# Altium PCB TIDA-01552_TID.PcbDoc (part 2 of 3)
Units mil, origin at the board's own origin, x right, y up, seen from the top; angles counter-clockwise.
Board outline 6250 x 2150 mil, 4 copper layers (Top Layer, Signal Layer 1, Signal Layer 2, Bottom Layer), stack 62.6 mil thick; 251 components, 249 nets, 926 pads, 730 vias.
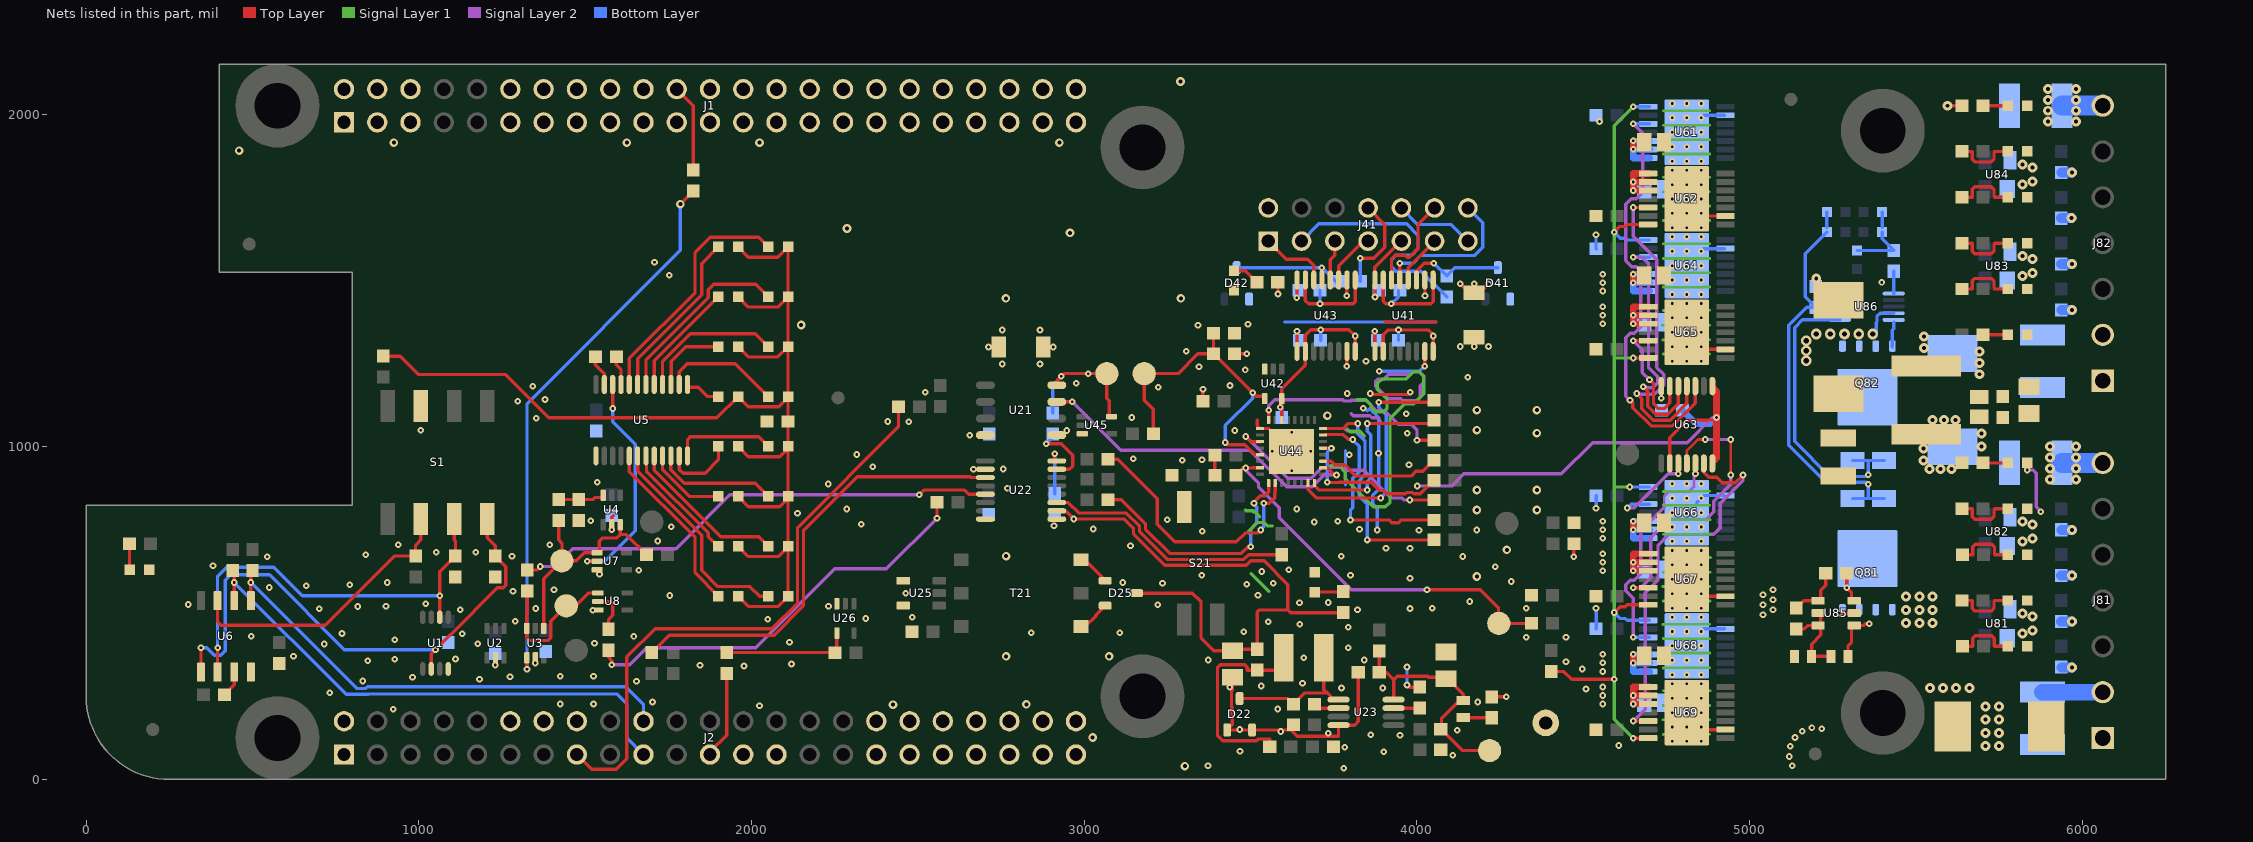
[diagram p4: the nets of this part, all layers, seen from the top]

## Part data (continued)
R75: "RES, 16.5 k, 1%, 0.1 W, 0603", Manufacturer=Vishay-Dale, Power_W=0.1, Supplier Part Number 1=541-16.5KHCT-ND, TempCo="100 ppm/C", Tolerance_%=1, Value1=1%, Value2=0.1W, Value_Code=16k5, ValueDisplayed=16.5k
R80 R82: "RES, 249, 1%, 0.1 W, 0603", Manufacturer=Vishay-Dale, Power_W=0.1, Supplier Part Number 1=541-249HCT-ND, TempCo="100 ppm/C", Tolerance_%=1, Value1=1%, Value2=0.1W, Value_Code=249R, ValueDisplayed=249
R83 R84 R85 R86 R87 R88 R89 R90 R91 R100: "RES, 10.0k ohm, 1%, 0.1W, 0603", Manufacturer=Vishay-Dale, Power_W=0.1, Supplier Part Number 1=541-10.0KHCT-ND, TempCo="100 ppm/C", Tolerance_%=1, Value1=1%, Value2=0.1W, Value_Code=10k0
R92: "RES, 95.3k ohm, 1%, 0.1W, 0603", Manufacturer=Vishay-Dale, Power_W=0.1, Supplier Part Number 1=541-95.3KHCT-ND, TempCo="100 ppm/C", Tolerance_%=1, Value1=1%, Value2=0.1W, Value_Code=95k3
R93: "RES, 8.06k ohm, 1%, 0.1W, 0603", Manufacturer=Vishay-Dale, Power_W=0.1, Supplier Part Number 1=541-8.06KHCT-ND, TempCo="100 ppm/C", Tolerance_%=1, Value1=1%, Value2=0.1W, Value_Code=8k06
R94: "RES, 47.5k ohm, 1%, 0.1W, 0603", Manufacturer=Vishay-Dale, Power_W=0.1, Supplier Part Number 1=541-47.5KHCT-ND, TempCo="100 ppm/C", Tolerance_%=1, Value1=1%, Value2=0.1W, Value_Code=47k5
R95: "RES, 14.0k ohm, 1%, 0.1W, 0603", Manufacturer=Vishay-Dale, Power_W=0.1, Supplier Part Number 1=541-14.0KHCT-ND, TempCo="100 ppm/C", Tolerance_%=1, Value1=1%, Value2=0.1W, Value_Code=14k0
R96: "RES, 57.6k ohm, 1%, 0.1W, 0603", Manufacturer=Vishay-Dale, Power_W=0.1, Supplier Part Number 1=541-57.6KHCT-ND, TempCo="100 ppm/C", Tolerance_%=1, Value1=1%, Value2=0.1W, Value_Code=57k6
R97: "RES, 100 ohm, 1%, 0.1W, 0603", Manufacturer=Vishay-Dale, Power_W=0.1, Supplier Part Number 1=541-100HCT-ND, TempCo="100 ppm/C", Tolerance_%=1, Value1=1%, Value2=0.1W, Value_Code=100R
R98 R99: "RES, 0.01 ohm, 1%, 1W, 1206", Manufacturer=Vishay-Dale, Power_W=1, Supplier Part Number 1=WSLP-.01CT-ND, TempCo="75 ppm/C", Value1=1%, Value2=1W, Value_Code=R010
S1: "Switch, SPST 4 Pos, Top Actuated, SMT", CurrentRating_mA=100, Manufacturer="CTS Electrocomponents", Supplier Part Number 1=CT2194LPST-ND
S21: "Switch, Slide, SPST 2 poles, SMT", CurrentRating_mA=100, Manufacturer="CTS Electrocomponents", Supplier Part Number 1=CT2192LPST-ND
T21: "Transformer, 475uH, SMT", Manufacturer="Wurth Elektronik", Supplier Part Number 1=732-4458-1-ND
TP1 TP2 TP3 TP4 TP21 TP22 TP42 TP61 TP62 TP64: library part PogoPad, "Pad for Pogo Pin Connector"
TP41: "Test Point, Miniature, Black, TH", Manufacturer=Keystone, Supplier Part Number 1=5001K-ND
U1: "Dual 2-Input Exclusive-OR Gate, DCT0008A", Alternate Manufacturer="Texas Instruments"
U2: "Single 3-Input Positive-OR Gate, DCK0006A", Alternate Manufacturer="Texas Instruments"
U3: "1-OF-2 DECODER/DEMULTIPLEXER, DCK0006A", Alternate Manufacturer="Texas Instruments"
U4: "Configurable Multiple-Function Gate, DCK0006A", Alternate Manufacturer="Texas Instruments"
U5: "16-Channel Constant Current LED Driver with LED Open Detection, 3 to 5.5 V, -40 to 85 degC, 24-pin SOP (DBQ24), Green (RoHS & no Sb/Br)", Alternate Manufacturer=None, Alternate PartNumber=Equivalent, Manufacturer="Texas Instruments", Rating=Catalog, Supplier Part Number 1=296-34376-5-ND
U6: "256 kb I2C CMOS Serial EEPROM, SOIC-8", Manufacturer="ON Semiconductor", Supplier Part Number 1=CAT24C256WI-G-ND
U7 U8: "Single Bus Buffer Gate With 3-State Output, DCK0005A", Alternate Manufacturer="Texas Instruments", Alternate PartNumber=SN74LVC1G125DCKT
U21: "1 Mbps Dual Channels, 1 / 1, Digital Isolator, 3.3 V / 5 V, -40 to +105 degC, 8-pin SOIC (D), Green (RoHS & no Sb/Br)", Alternate Manufacturer=None, Alternate PartNumber=Equivalent, Insulation Rating(VRMS)=2500, Manufacturer="Texas Instruments", Rating=Catalog, Supplier Part Number 1=ISO7421DR-ND, Supply Voltage(s)(V)="3.3, 5"
U22 U41: "4242-VPK Small-Footprint and Low-Power Quad Channels Digital Isolators, DBQ0016A", Alternate Manufacturer="Texas Instruments", Alternate PartNumber=ISO7141CCDBQ
U23: "150 mA, 100V Step-Down Switching Regulator, 8-pin MSOP, Pb-Free", Manufacturer="Texas Instruments", PackageTopMarking=ZXTT*SLLB, PowerWise=Y, Supplier Part Number 1=LM5009MMTR-ND
U25: "Low-Noise 350 mA, 410 kHz Transformer Driver, DBV0005A (SOT-23-5)", Alternate Manufacturer="Texas Instruments", Alternate PartNumber=SN6501DBVT
U26 U42 U45: "SINGLE BUFFER/DRIVER WITH OPEN-DRAIN OUTPUT, DCK0005A (SOT-SC70-5)", Alternate Manufacturer="Texas Instruments", Alternate PartNumber=SN74LVC1G07DCKT
U43: "4242-VPK Small-Footprint and Low-Power Quad Channels Digital Isolators, DBQ0016A", Alternate Manufacturer="Texas Instruments", Alternate PartNumber=ISO7141FCCDBQ
U44: "16 MHz Mixed Signal Microcontroller with 2 KB Flash, 256 B SRAM and 24 GPIOs, -40 to 105 degC, 32-pin QFN (RHB), Green (RoHS & no Sb/Br)", Alternate Manufacturer="Texas Instruments", Alternate PartNumber=Equivalent, Frequency(MHz)=16, Pin/Package="28TSSOP, 32QFN, 32WQFN", Temp Sensor=Yes
U61 U62 U64 U65 U66 U67 U68 U69: library part CMP-0077266-1, "40 V, 80 mOhm Single-Channel High-Side Switch, PWP0014C (TSSOP-14)", Alternate Manufacturer="Texas Instruments", Alternate PartNumber=TPS27S100BPWPT
U63: "8-BIT PARALLEL-OUT SERIAL SHIFT REGISTERS, PW0014A", Alternate Manufacturer="Texas Instruments", Alternate PartNumber=SN74LV164APWT
U81 U82 U83 U84: "ESD Suppressor Diode Arrays, 70V, SMD", Manufacturer=Littelfuse, Supplier Part Number 1=F5915CT-ND
U85: "LM5050-1 High Side OR-ing FET Controller, DDC0006A", Alternate Manufacturer=None, Manufacturer="Texas Instruments"
U86: "Positive High Voltage Hot Swap / Inrush Current Controller with Power Limiting, 10-pin MSOP, Pb-Free", Manufacturer="National Semiconductor", PackageTopMarking=ZXTT*SNBB, PowerWise=N, Supplier Part Number 1=LM5069MM-2TR-ND
ZZ1: library part AssemblyNoteLabel
ZZ2 ZZ3 ZZ4: library part AssemblyNote

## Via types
v1: diameter 20, hole 8, Top Layer to Bottom Layer, tented both sides, 418 vias
v2: diameter 19.68, hole 7.87, Top Layer to Bottom Layer, 77 vias
v3: diameter 30, hole 12, Top Layer to Bottom Layer, tented both sides, 73 vias
v4: diameter 19.68, hole 7.87, Top Layer to Bottom Layer, tented both sides, 48 vias
v5: diameter 39.37, hole 19.68, Top Layer to Bottom Layer, 36 vias
v6: diameter 26, hole 12, Top Layer to Bottom Layer, tented both sides, 31 vias
v7: diameter 20, hole 7.87, Top Layer to Bottom Layer, tented both sides, 12 vias
v8: diameter 20, hole 8, Top Layer to Bottom Layer, 12 vias
v9: diameter 30, hole 12, Top Layer to Bottom Layer, 9 vias
v10: diameter 32, hole 16, Top Layer to Bottom Layer, tented both sides, 8 vias
v11: diameter 50, hole 20, Top Layer to Bottom Layer, tented both sides, 4 vias
v12: diameter 26, hole 8, Top Layer to Bottom Layer, tented both sides, 2 vias

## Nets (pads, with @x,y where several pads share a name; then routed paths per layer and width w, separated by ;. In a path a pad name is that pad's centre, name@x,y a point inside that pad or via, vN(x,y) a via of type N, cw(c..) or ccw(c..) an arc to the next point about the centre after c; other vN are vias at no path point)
24V_Field: C89.1 C90.1 C91.1 C94.1 C95.1 C96.1 D90.1 D92.1 J81.7 J82.7 Q81.1 Q81.2 Q81.3 R91.1 U85.4 | length 377
  Top Layer w10: D92.1@5295.59,389.68 5295.59,401.59 5306,412 5306,462.6 5341.6,462.6 5347,468 v1(5359,468)
  Bottom Layer w60: C90.1@5938.74,951.39 J81.7@6061,951.39 ; C89.1@5938.74,2025.39 J82.7@6061,2025.39
  other v3: 5470,470 5510,470 5550,470 5470,510 5510,510 5550,510 5470,550 5510,550 5550,550 5902,902 5980,902 5540,933 5573,933 5606,933 5902,935 5980,935 5522,959.2 5902,968 5980,968 5522,994.2 5697,1001 5902,1001 5980,1001 5697,1040 5550,1080 5584,1080 5618,1080 5897,1977 5980,1977 5897,2010 5980,2010 5897,2043 5980,2043 5897,2076 5980,2076
24V_LOCAL: C61.1 C62.1 C64.1 C65.1 C67.1 C68.1 C70.1 C71.1 C100.1 D94.1 L21.1 Q82.1 Q82.2 Q82.3 R72.2 R100.1 U61.8 U61.9 U61.10 U62.8 U62.9 U62.10 U64.8 U64.9 U64.10 U65.8 U65.9 U65.10 U66.8 U66.9 U66.10 U67.8 U67.9 U67.10 U68.8 U68.9 U68.10 U69.8 U69.9 U69.10 U81.4 U82.4 U83.4 U84.4 U86.9 | length 6513.9
  Top Layer w10: L21.1@4225,248.5 v1(4268.5,248.5) ; v1(4471,669) 4471,708.5 R72.2@4471.5,709 ; v3(5595,2025) 5638.09,2025 R100.1@5638.5,2024.58
  Top Layer w18: v1(4650,226.74) U69.10@4698.8,226.74 ; v1(4650,627.41) U67.10@4698.8,627.41 ; v1(4650,1369.74) U65.10@4698.8,1369.74 ; v1(4650,1770.41) U62.10@4698.8,1770.41
  Top Layer w20: v1(4650,226.74) 4650,278 ; v1(4650,252.33) U69.9@4698.8,252.33 ; 4650,277.92 U69.8@4698.8,277.92 ; v1(4650,350) v1@4650,375.67 ; v1(4650,627.41) 4650,678.67 ; v1(4650,653) U67.9@4698.8,653 ; 4650,678.59 U67.8@4698.8,678.59 ; v1(4650,750.97) v1@4650,776.67 ; v1(4650,1369.74) v1(4650,1395.33) ; v1(4650,1493.3) v1@4650,1519.08 ; v1(4650,1770.41) 4650,1821.67 ; v1(4650,1796) U62.9@4698.8,1796 ; 4650,1821.59 U62.8@4698.8,1821.59 ; v1(4650,1893.97) v1(4650,1919.56) ; U65.9@4698.8,1395.33 v1(4650,1395.33) ; U65.8@4698.8,1420.92 4650,1420.92 v1(4650,1395.33)
  Signal Layer 1 w8: 4738,1365 4738.49,1365.49 4863.15,1365.49 4863.64,1365 4880,1365 ; 4739,180 4739.19,179.81 4880.19,179.81 ; 4739,466 4739.13,466.13 4879.13,466.13 ; 4739,580 4880,580 ; 4739,1321 4740.18,1322.18 4863.15,1322.18 4863.33,1322 4880,1322 ; 4740,135 4740.88,135.88 4879.88,135.88 ; 4740,222 4740.49,222.49 4879.49,222.49 ; 4740,267 4740.58,266.42 4880.58,266.42 ; 4740,335 4741.21,336.21 4880.21,336.21 ; 4740,380 4880,380 ; 4740,424 4740.55,423.45 4879.55,423.45 ; 4740,536 4740.54,536.54 4880.54,536.54 ; 4740,623 4740.16,623.16 4881.16,623.16 ; 4740,825 4740.89,824.11 4879.89,824.11 4880,824 ; 4740,865 4741.8,866.8 4879.8,866.8 ; 4740,1279 4879,1279 ; 4740,1410 4740.58,1409.42 4863.15,1409.42 4863.73,1410 4880,1410 ; 4740,1480 4740.17,1479.83 4863.15,1479.83 4863.32,1480 4880,1480 ; 4740,1523 4880,1523 ; 4740,1566 4880,1566 ; 4740,1610 4740.25,1609.75 4863.15,1609.75 4863.39,1610 4880,1610 ; 4740,1680 4880,1680 ; 4740,1724 4740.53,1723.47 4879.53,1723.47 ; 4740,1767 4740.22,1766.78 4878.22,1766.78 ; 4740,1810 4880,1810 ; 4740,1880 4880,1880 ; 4740,1923 4740.18,1923.18 4863.15,1923.18 4863.33,1923 4880,1923 ; 4740,1966 4740.49,1966.49 4863.15,1966.49 4863.64,1966 4880,1966 ; 4740,2010 4880,2010 ; 4741,667 4882,667 ; 4741,737 4882,737 ; 4741,781 4741.19,780.81 4863.15,780.81 4863.34,781 4881,781
  Bottom Layer w10: v10@5380,1339 5380,1373.18 5382.5,1375.68 5382.5,1391.68 5392.13,1401.31 U86.9@5432.71,1401.31
  Bottom Layer w18: v1(4650,376) U68.10@4698.8,376 ; v1(4650,776.56) U66.10@4698.8,776.56 ; v1(4650,1519) U64.10@4698.8,1519 ; v1(4650,1919.56) U61.10@4698.8,1919.56
  Bottom Layer w20: v1(4650,226.74) v1(4650,252.33) ; v1(4650,376) v1(4650,350) ; v1(4650,627.41) v1(4650,653) ; v1(4650,776.56) v1(4650,750.97) ; v1(4650,1369.74) v1(4650,1395.33) ; v1(4650,1519) v1@4650,1493 ; v1(4650,1770.41) v1(4650,1796) ; v1(4650,1919.56) v1(4650,1893.97) ; U68.8@4698.8,324 4650,324 v1(4650,350) ; U68.9@4698.8,350 v1(4650,350) ; U66.8@4698.8,725 4650,725 v1(4650,750.97) ; U66.9@4698.8,751 v1(4650,750.97) ; U64.8@4698.8,1468 4650,1468 v1@4650,1493 ; U64.9@4698.8,1493 v1@4650,1493 ; U61.8@4698.8,1868 4650,1868 v1(4650,1893.97) ; U61.9@4698.8,1893.97 v1(4650,1893.97)
  other v1: 4558,226.74 4558,252.33 4558,277.92 4558,324.71 4558,350.51 4558,376 4283,595 4558,627.51 4235,639 4558,653 4558,678 4558,725.02 4180,750 4558,750.51 4558,776 4153,1209 4558,1370.02 4558,1395.51 4558,1421 4558,1468.02 4558,1493.51 4558,1519
  other v3: 5850,490 5820,499 5850,766 5820,775 5850,1564 5820,1573 5850,1840 5820,1849
  other v10: 5170,1259 5170,1289 5170,1319 5200,1339 5242.5,1339 5285,1339 5327.5,1339 5370,1339
+3.3V_ISO: C22.1 C24.1 C30.1 C43.1 C44.1 C45.1 C63.1 D25.3 R30.2 R32.1 R46.1 R47.1 TP22.1 U21.8 U22.10 U22.16 U41.10 U41.16 U42.5 U43.10 U43.16 U44.30 U45.5 U63.1 U63.9 U63.14 | length 6615
  Top Layer w10: U21.8@2904.49,1185 v1(2931,1211.51) 2939.49,1220 v1(3012,1220) 3032.7,1220 ; U22.10@2909.41,807.5 2943.5,807.5 2947.75,803.25 2948.52,803.25 2968.76,783 3118.89,783 3148.16,753.73 3148.16,737.73 3242.39,643.5 3486.99,643.5 3500.48,657 3541,657 3612,586 3612,509.5 ; U22.16@2909.41,957.5 2909.41,977.37 v1(2911.04,979) ; 3068,1184.7 3068,1146 3075.4,1138.6 U45.5@3075.4,1090.59 ; 3177.42,560 3325,560 3351,534 3351,425 3389,387 C30.1@3445,387 3449.5,391.5 R30.2@3520,391.5 3520,503.5 3526,509.5 3612,509.5 ; R46.1@3356.5,1137 v1@3356.5,1172.5 ; R47.1@3451.5,1280 v1(3488,1280) ; U44.30@3593.47,1080.49 3593.47,1151.48 3593.59,1151.6 3593.59,1174.64 3664.5,1245.55 3664.5,1294.59 3664.5,1335.2 3681.3,1352 v1(3710.5,1352) 3795.48,1352 v1(3814.5,1332.98) U43.16@3814.5,1294.59 ; R32.1@3778,501.5 3620,501.5 3612,509.5 ; U41.10@3898.5,1294.59 3898.5,1336.01 3913.49,1351 4034,1351 4048.5,1336.5 U41.16@4048.5,1294.59 ; U63.9@4759.82,953.94 4759.82,1027.82 4812.5,1080.5 4852.68,1080.5 4853.18,1080 4871.82,1080 4872.32,1080.5 4892.5,1080.5 v1(4900,1088)
  Top Layer w20: U63.1@4891.06,1175.06 4900,1166.12 v1(4900,1088) 4900,966.17 U63.14@4891.41,957.59
  Signal Layer 2 w10: 3785,1053 3790.5,1047.5 3826.5,1047.5 3842,1032 ; 3802,1100 3808.5,1093.5 3858.32,1093.5 3864.82,1087 3879,1087 3890,1076 ; v8(4001,882) 4104.18,882 4140.68,918.5 4433.76,918.5 4527.76,1012.5 4812.5,1012.5 4888,1088 v1(4900,1088) ; 3875.11,1183.07 3913.59,1144.59 3951.41,1144.59 3957,1139 4000,1139 4010,1149 4010,1183.18 4020.5,1193.68 4020.5,1212.32 4007.32,1225.5 3988.68,1225.5 3981.18,1218 3915.1,1218 3899.6,1202.5 3882.5,1202.5 3875.11,1195.11 3875.11,1183.07
  Signal Layer 1 w10: 3484,810 3486.5,807.5 3507.5,807.5 3507.5,804.5 3512.5,804.5 3528,789 ; 3494,740 3494,746 3520.5,772.5 3539.32,772.5 3549.82,762 3565,762 ; 3502,618 3554,566 ; 3740.5,943 3766.05,943 3783.49,925.56 3783.49,904.69 3868.5,819.68 3905,819.68 3919,833.68 3919,1085.7 3962.82,1129.52 3990.52,1129.52 4020.5,1159.5 4020.5,1212.32 4007.32,1225.5 3988.68,1225.5 3966.73,1203.55 3893.55,1203.55 3881,1191 3881,1173 3909.6,1144.4 3909.6,1114.6 3900,1105 3876,1105 3862,1119 3862,1124.82 3845.82,1141 3820,1141 ; 3791,1053 3799,1045 3829,1045 3840,1034
  Bottom Layer w10: C22.1@2905,1101.5 2905,1185.51 v1(2931,1211.51) ; C24.1@2911.04,859.02 v1(2911.04,979) ; v1(3589,1119) 3594,1114 C44.1@3594,1087.5 ; C45.1@3710.5,1320 v1@3710.5,1353.5 ; C43.1@3944.5,1320 v1(3944.5,1352)
  Bottom Layer w20: C63.1@4797.5,1110 4838.5,1069 4881,1069 v1(4900,1088)
  other v1: 3821,510 3979,514 4046,515 3733,532 3979,605 3800,614 3772,671 3907,695 3979,695 3827,752 3691,774 2968,783 3294,960 3452,1049 3357,1173 4048.5,1332.98
+3.3V_TOOL: C42.1 C46.1 J41.2 R48.2 U41.1 U41.7 U43.1 U43.7 | length 661.2
  Top Layer w10: R48.2@3581.5,1495 3582,1494.5 v1(3582,1459) ; U43.7@3664.5,1493.41 3664.5,1439.5 3674,1430 v1(3708.5,1430) 3808,1430 3814.5,1436.5 U43.1@3814.5,1493.41 ; U41.7@3898.5,1493.41 3898.5,1437.5 3906,1430 4042,1430 4048.5,1436.5 U41.1@4048.5,1493.41
  Bottom Layer w10: v1(3708.5,1430) C46.1@3708.5,1470 ; v1(3923,1430) 3944.5,1451.5 C42.1@3944.5,1470
/CS0: R6.2 U22.5 | length 1489.4
  Top Layer w10: R6.2@1326,629.5 1354.5,629.5 v1(1365,640) ; v1(2504,856) 2518,870 2640.09,870 2652.59,857.5 U22.5@2710.59,857.5
  Signal Layer 2 w10: v1(1365,640) 1408,640 1462,694 1773,694 1935,856 v1(2504,856)
/CS0_ISO: R25.1 U44.9 | length 741.8
  Top Layer w10: R25.1@3071.5,841 3111.44,841 3183.91,768.54 3183.91,752.54 3257.19,679.25 3472.18,679.25 3492.93,700 v1(3500,700) ; v1(3510,830) 3510,833.35 3529.53,852.87 3542.87,852.87 3554.1,864.1 U44.9@3554.1,891.51
  Bottom Layer w10: v1(3500,700) 3500,752.35 3518,770.35 3518,818.65 3510,826.65 v1(3510,830)
/CS1: R14.2 R17.1 TP4.1 U3.4 U4.3 U7.1 | length 690.3
  Top Layer w10: U3.4@1375.59,447.4 1375.59,602.59 TP4.1@1430,657 1473,657 1497,681 1542.6,681 1542.6,716.6 1552,726 1595.38,726 1605.59,736.21 ; R14.2@1420,758.82 1420,720 1430,710 TP4.1@1430,658 ; U4.3@1605.59,755.87 1605.59,736.21 ; R17.1@1684.5,675 1623.29,736.21 1605.59,736.21
/SDRDY: U21.7 U44.18 | length 1024
  Top Layer w10: U21.7@2904.49,1135 2904.98,1135.49 v1(2963.8,1135.49) ; U44.18@3717.49,936.79 3730.5,936.79 3752.29,915 v1(3758,915)
  Signal Layer 2 w10: v1(2963.8,1135.49) 3109.29,990 3498,990 3608,880 3685.18,880 3720.68,915.5 3739.32,915.5 3739.82,915 v1(3758,915)
/XSDRDY: R1.2 R21.1 U26.4 | length 392.8
  Top Layer w10: R1.2@1925,381.5 2250.01,381.5 2256.41,387.9 U26.4@2256.41,446.6
AIN0: J2.39
AIN1: J2.40
AIN2: J2.37
AIN3: J2.38
AIN4: J2.33
AIN5: J2.36
AIN6: J2.35
CLKOUT2: J2.41
CSENSE: C69.1 R81.1 TP64.1 U44.7 | length 1163.7
  Top Layer w10: C69.1@3455.5,915 3476.49,936 v1(3484.98,936) 3506.02,936 3506.81,936.79 U44.7@3528.51,936.79 ; v1(4030,570) 4190,570 4245.04,514.96 TP64.1@4245.04,494.96 ; TP64.1@4246,469 4343.5,469 R81.1@4344.5,470
  Signal Layer 2 w10: v1(3484.98,936) 3484.98,930.02 3523.87,891.13 3523.87,878.5 3585.81,816.56 3585.81,786.91 3802.72,570 v1(4030,570)
"CURRENT SENSE": R80.2 U61.14 U62.14 U64.14 U65.14 U66.14 U67.14 U68.14 U69.14 | length 2914.4
  Top Layer w10: R80.2@4404,324.5 4441.5,324.5 4464.69,301.31 v1(4593,301.31) ; v1(4593,502) 4610.47,519.47 4626.36,519.47 4631.89,525 U67.14@4698.8,525 ; v1(4593,1645) 4610.09,1662.09 4626.51,1662.09 4632.46,1668.04 U62.14@4698.8,1668.04 ; v1(4649.8,124.38) U69.14@4698.59,124.38 ; v1(4650.17,1267) 4699.17,1267 U65.14@4698.8,1267.38
  Signal Layer 1 w10: 4594,879 v1(4639,879) ; v1(4649.8,124.38) 4593,181.17 4593,1267 ; v1(4650,2022) 4593,1965 v1(4593,1645) 4593,1267 ; v1(4650.17,1267) 4593,1267
  Bottom Layer w10: v1(4593,502) 4611.17,483.83 4626.36,483.83 4631.94,478.25 U68.14@4698.8,478.25 ; v1(4593,1645) 4610.8,1627.2 4626.51,1627.2 4632.46,1621.25 U64.14@4698.8,1621.25 ; v1(4639,879) U66.14@4698.8,878.92 ; v1(4650,2022) 4698.71,2022 U61.14@4698.8,2021.92
D0: R63.1 U44.15 | length 726.9
  Top Layer w10: U44.15@3672.21,891.51 3672.21,872.51 3698.72,846 v7(3891,846) ; v7(3885,1134) 4034.52,1134 4039.52,1129 4047.52,1137 4048.01,1136.51 R63.1@4051.5,1140
  Bottom Layer w10: v7(3885,1134) 3885,1119 3908,1096 3908,863 v7(3891,846)
D1: R64.1 U44.16 | length 586.5
  Top Layer w10: U44.16@3691.9,891.51 3691.9,883.63 3705.53,870 v7(3850,870) ; v7(3850,1070) 4041.5,1070 R64.1@4051.5,1080
  Bottom Layer w10: v7(3850,870) 3850,895.25 3861.13,906.38 3861.13,1035.87 3850,1047 v7(3850,1070)
D2: R68.1 U44.32 | length 618.1
  Top Layer w10: U44.32@3554.1,1080.49 v1@3554.1,1109.9 ; v7(4000,1020) R68.1@4051.5,1020
  Signal Layer 2 w10: v1(3554,1110) 3554,1123 3572.5,1141.5 3776.68,1141.5 3780.68,1137.5 3799.32,1137.5 3801.82,1140 3846.82,1140 3877.82,1109 3903,1109 3943.88,1068.12 3982.88,1068.12 4000,1051 v7(4000,1020)
D3: R69.1 U44.19 | length 378.7
  Top Layer w10: U44.19@3717.49,956.47 3742.18,956.47 3752.78,945.87 3782.47,945.87 3816.35,912 3982,912 3996,926 4017.5,926 R69.1@4051.5,960 R69.1@4057.9,960
D4: R73.1 U44.21 | length 489.4
  Top Layer w10: U44.21@3717.49,995.84 v7(3742.84,995.84) ; v7(3730,893) 3730.5,892.5 3767.32,892.5 3767.82,893 3863,893 3887.5,868.5 3900.32,868.5 3909.82,859 3965.18,859 3968.68,862.5 3987.32,862.5 3990.82,859 4010.5,859 R73.1@4051.5,900
  Bottom Layer w10: v7(3730,893) 3730,983 v7(3742.84,995.84)
D5: R74.1 U44.3 | length 722.3
  Top Layer w10: v1(3485,1031) 3500.47,1015.53 U44.3@3528.51,1015.53 ; v7(3978,840) R74.1@4051.5,840
  Signal Layer 2 w10: v1(3485,1031) 3610.79,905.21 3682.14,905.21 3714.43,937.5 3775.94,937.5 3784.44,929 3839.82,929 3922.82,846 3955.94,846 3961.94,840 v7(3978,840)
D6: R78.1 U44.23 | length 614.9
  Top Layer w10: U44.23@3717.49,1035.21 3724.59,1035.21 3726.12,1036.75 3778.25,1036.75 3793,1022 v7(3807,1022) ; v7(3800,780) 3915.96,780 3923.83,772.13 3945.47,772.13 3953.35,780 R78.1@4051.5,780
  Bottom Layer w10: v7(3800,780) 3800,809 3807,816 3807,906 3826,925 3826,1001 3807,1020 v7(3807,1022)
D7: R79.1 U44.24 | length 689
  Top Layer w10: U44.24@3717.49,1054.9 3778.9,1054.9 3794,1070 v7(3822,1070) ; v7@3850.1,720 4049.5,720 4050.5,721 R79.1@4051.5,720
  Bottom Layer w10: v7(3822,1070) 3822,1039.35 3843.5,1017.85 3843.5,915.19 3826.13,897.82 3826.13,850.87 3850,827 v7(3850,720)
DGND: C1.2 C2.2 C3.2 C4.2 C5.2 C6.2 C7.2 C8.1 C21.2 C23.2 C27.2 C31.2 D1.2 J1.1 J1.2 J2.1 J2.2 J2.43 J2.44 J2.45 J2.46 R9.1 R10.1 R15.2 S1.7 U1.4 U2.2 U3.2 U4.2 U5.1 U5.21 U6.4 U7.3 U8.3 U21.4 U22.2 U22.8 U25.4 U25.5 U26.3 | length 119.5
  Top Layer w10: v1(1230,344) U2.2@1230,355.87 ; U4.2@1580,765.71 1580,789 1584,793 ; R15.2@1593.5,1252.3 1593.5,1246.5 1607.5,1232.5 U5.21@1607.5,1179.41
  other v1: 923,211 2024,222 1425,227 1525,227 1702,233 732,261 1654,295 831,296 1182,301 981,307 1274,309 1425,310 1525,310 1977,341 1845,343 2120,347 1350,350 846,357 928,361 1110,362 623,370 716,407 1177,408 1528,409 2114,412 928,420 1646,430 496,431 1130,438 769,439 1290,476 2049,482 2343,484 2483,488 1522.87,508.95 1124,510 701,513 1351,514 816,520 901,521 2231,521 307,526 1021,528 1754,553 2463,560 1283,566 1406,570 550,577 661,582 792,585 905,592 1543,617 1661,629 381,642 544,669 1280,671 840,675 1052,683 1171,683 938,706 1393,706 1580,751 1759,760 2330,767 1517,778 2138,800 2286,813 2769,875 2230,888 1536,893 2666.95,932.5 2756,933 2364,940 2316,977 2656,1035 1006,1050 2472,1075 2409,1076 1353,1086 1297,1137 1379,1142 2522,1164 1342,1182 2753,1249 2712,1300 2753,1351 1753,1516 1708,1555
  other v6: 3302,40 3025,126 2425,225 2826,226 2765,370 3075,370 2765,671 2149,1366 2764,1446 3290,1446 2957,1643 2287,1656 460,1890 925,1914 1625,1914 2024,1914 2925,1914 3289,2098
  other v8: 1718,717
EHRPWM1A: J2.14
EHRPWM1B: J2.16
EHRPWM2A: J1.19
EHRPWM2B: J1.13
EN0: U61.12 U63.3 | length 1293.2
  Top Layer w10: v8(4640,1140) 4648.18,1131.82 4648.18,1117.75 4703.43,1062.5 4767.95,1062.5 4836.59,1131.14 U63.3@4836.59,1178.35
  Signal Layer 2 w10: v8(4640,1140) 4627.5,1152.5 4627.5,1327.88 4640.68,1341.06 4653.14,1341.06 4672.5,1360.42 4672.5,1528.32 4659.32,1541.5 4645.27,1541.5 4627,1559.77 4627,1729 4643.6,1745.6 4659.6,1745.6 4679,1765 4679,1941.74 v1(4650,1970.74)
  Bottom Layer w10: v1(4650,1970.74) U61.12@4698.8,1970.74
EN1: U62.12 U63.4 | length 985.1
  Top Layer w10: v1(4650,1719.22) U62.12@4698.8,1719.22 ; v8(4660,1160) 4676,1144 4676,1114.68 4710.68,1080 4760.7,1080 4811,1130.3 U63.4@4811,1178.35
  Signal Layer 2 w10: v1(4650,1719.22) 4650,1633 4720.84,1562.16 4720.84,1238.16 4741.5,1217.5 4741.5,1184.93 4725.07,1168.5 4724.68,1168.5 4713.68,1157.5 4662.5,1157.5 v8(4660,1160)
EN2: U63.5 U64.12 | length 751.5
  Top Layer w10: v8(4680,1180) 4693.5,1166.5 4693.5,1121.93 4717.93,1097.5 4753.45,1097.5 4785.41,1129.46 U63.5@4785.41,1178.35
  Signal Layer 2 w10: v1(4650,1570.07) 4675.93,1570.07 4696,1550 4696,1238 4724,1210 4724,1192.18 4717.82,1186 4717.43,1186 4708.93,1177.5 4690.68,1177.5 4688.18,1180 v8(4680,1180)
  Bottom Layer w10: v1(4650,1570.07) U64.12@4698.8,1570.07
EN3: U63.6 U65.12 | length 371.5
  Top Layer w10: v1(4650,1318.56) U65.12@4694.86,1318.56 U65.12@4698.8,1318.56 ; v8(4699,1201) 4711,1189 4711,1129.18 4725.18,1115 4742.82,1115 4759.82,1132 U63.6@4759.82,1178.35
  Signal Layer 2 w10: v1(4650,1318.56) 4677,1291.56 4677,1223 v8(4699,1201)
EN4: U63.10 U66.12 | length 302.5
  Top Layer w10: v1(4785,919) 4785,953.53 U63.10@4785.41,953.94
  Signal Layer 2 w10: v1(4632.02,815.85) 4651.85,815.85 4755,919 v1(4785,919)
  Bottom Layer w10: v1(4632.02,815.85) 4643.91,827.74 U66.12@4698.8,827.74
EN5: U63.11 U67.12 | length 875.2
  Top Layer w8: U63.11@4811,953.94 4811,988.5 4844.5,1022 v8(4866,1022) ; v8(4943,915) v8(4943,1022)
  Top Layer w10: v1(4650,576.22) U67.12@4698.8,576.22
  Signal Layer 2 w8: 4758,781 4758.19,780.81 4868.81,780.81 ; v8(4866,1022) v8(4943,1022)
  Signal Layer 2 w10: v1(4650,576.22) 4673.22,576.22 4703,606 4703,726 4758,781 ; 4868.81,780.81 4892,804 4892,837 4943,888 v8(4943,915)
EN6: U63.12 U68.12 | length 714.6
  Top Layer w10: U63.12@4836.59,953.94 4837,953.53 v8(4837,919)
  Signal Layer 2 w8: 4743,818 4743,850.95 4758.85,866.8 4819.22,866.8 4832.34,879.92 4832.34,914.34 v8(4837,919)
  Signal Layer 2 w10: v1(4650,427.07) 4650,544.4 4627.5,566.9 4627.5,585.54 4640.68,598.72 4653.14,598.72 4672.5,618.09 4672.5,747.5 4743,818
  Bottom Layer w10: v1(4650,427.07) U68.12@4694.86,427.07 U68.12@4698.8,427.07
EN7: U63.13 U69.12 | length 1175
  Top Layer w10: v1(4650,175.56) U69.12@4698.8,175.56 ; U63.13@4862.18,953.94 4862.18,923.3 4877.5,907.98 4900.63,907.98 4917.16,891.45 4956.45,891.45 v8(4980,915)
  Signal Layer 2 w8: 4755,735 4756.88,736.88 4865.88,736.88
  Signal Layer 2 w10: v1(4650,175.56) 4685.65,211.21 4685.65,561.65 4724.39,600.39 4724.39,704.39 4755,735 ; 4865.88,736.88 4891.24,736.88 4911,756.64 4911,830.75 4980,899.75 v8(4980,915)
GND_DEBUG: C41.2 C42.2 C46.2 D41.1 D42.1 D44.2 J41.9 U41.2 U41.8 U43.2 U43.8 | length 441.8
  Top Layer w10: v1@3639.5,1448.5 U43.8@3639.5,1493.41 ; v1(3789,1454) 3789,1492.91 U43.2@3789.5,1493.41 ; v1(3874,1450) 3874,1492.91 3873.5,1493.41 3873.5,1540.13 3951.37,1618 J41.9@3953,1618 ; U41.2@4023.5,1493.41 4024,1492.91 v1(4024,1454) ; v1(4130,1490) 4166.91,1453.09 4172,1453.09 4178.09,1453.09 v1(4215,1490)
  other v1: 3639,1448 4172,1490
GND_EARTH: C81.2 C82.2 C83.2 C84.2 C85.2 C86.2 C87.2 C88.2 C89.2 C90.2 C92.2 C93.2 J81.1 J82.1 | length 256.2
  Bottom Layer w10: C87.2@5935.93,1686.84 C87.2@5936.1,1687 ; C81.2@5936,337.5 C81.2@5936.5,337 ; C82.2@5936,475.17 C82.2@5936.17,475 ; C83.2@5936,612.84 C83.2@5936.16,613 ; C84.2@5936,750.5 C84.2@5936.5,750 ; C85.2@5936,1411.5 C85.2@5936.5,1411 ; C86.2@5936,1549.17 C86.2@5936.17,1549 ; C88.2@5936,1824.5 C88.2@5936.5,1824
  Bottom Layer w30: C87.2@5936.1,1687 v9(5967,1687) ; C82.2@5936.17,475 v9(5968,475) ; C83.2@5936.16,613 v9(5968,613) ; C86.2@5936.17,1549 v9(5968,1549) ; C81.2@5936.5,337 v9(5968,337) ; C84.2@5936.5,750 v9(5968,750) ; C85.2@5936.5,1411 v9(5968,1411) ; C88.2@5936.5,1824 v9(5968,1824)
GND_SIGNAL: C22.2 C24.2 C25.1 C27.1 C28.2 C29.2 C30.2 C41.1 C43.2 C44.2 C45.2 C47.1 C61.2 C62.2 C63.2 C64.2 C65.2 C66.2 C67.2 C68.2 C69.2 C70.2 C71.2 C91.2 C92.1 C93.1 C94.2 C95.2 C96.2 C98.2 C99.2 C100.2 D22.1 D22.2 D24.2 D43.2 D81.2 D82.2 D83.2 D84.2 D85.2 D86.2 D87.2 D88.2 D89.1 D90.2 D91.2 D93.1 D94.2 D95.2 J81.2 J82.2 R31.1 R33.1 R34.1 R35.1 R61.2 R62.2 R66.2 R67.2 R70.2 R71.2 R75.1 R76.2 R77.2 R82.1 R93.1 R95.1 R96.1 S21.4 TP41.1 U21.5 U22.9 U22.15 U23.4 U41.9 U41.15 U42.3 U43.9 U43.15 U44.1 U44.33 U45.3 U61.2 U61.15@4811,1945.15 U62.2 U62.15@4811,1744.81 U63.7 U64.2 U64.15@4811,1544.48 U65.2 U65.15@4811,1344.15 U66.2 U66.15@4811,802.15 U67.2 U67.15@4811,601.81 U68.2 U68.15@4811,401.48 U69.2 U69.15@4811,201.15 U86.5 | length 4080
  Top Layer w10: v1(2886,1008.98) 2931.02,1008.98 2965,975 2965,942 2955.5,932.5 U22.15@2909.41,932.5 ; 3392.5,933.7 C66.2@3392.5,975 ; C30.2@3445,307 3445,267.49 3442.31,264.8 3442.31,219 3445,216.32 3445,164.16 D22.1@3429.6,148.76 D22.2@3504.4,148.76 3621.24,148.76 3640.43,129.57 3764.32,129.57 U23.4@3764.32,163.3 3812.3,163.3 3823.5,174.5 C29.2@3823.5,322 ; 3519.66,1080.66 3519.66,1063.75 U44.1@3528.51,1054.9 3554.1,1054.9 U44.33@3565,1044 ; U43.9@3639.5,1294.59 v1(3639.5,1347) ; v1(3788.86,1242.53) 3788.86,1293.95 U43.15@3789.5,1294.59 ; v1(3860,1160) 3862.87,1157.13 3973.13,1157.13 v1(3980,1164) ; U41.9@3873.5,1294.59 v1@3873.5,1346.5 ; 3903,1375 4056,1375 ; v1@3976.5,277.5 C25.1@4008,277.5 ; v1@4023.5,1243.17 U41.15@4023.5,1294.59 ; U69.15@4860.21,151.94 4862.18,149.97 U69.2@4923.2,149.97 ; U67.15@4860.21,552.6 4862.18,550.63 U67.2@4923.2,550.63 ; U65.15@4860.21,1294.94 4862.18,1292.97 U65.2@4923.2,1292.97 ; U62.15@4860.21,1695.6 4862.18,1693.63 U62.2@4923.2,1693.63
  Signal Layer 2 w10: v1(5834,930) 5852,930 5861,921 5861,819 v1(5875,805)
  Bottom Layer w10: v1(2886,1008.98) 2905,1027.98 C22.2@2905,1038.5 ; 3602,1375 4056,1375 ; 3785,885 3785,988 ; v1(3838,1116) 3841,1116 3845,1112 3846,1113 3851,1108 3858,1115 3885,1088 3885,872.35 3867.5,854.85 3867.5,828.7 3881,815.2 v1(3881,750) ; v1(3887,1227) 4007.33,1227 v1(4022.86,1242.53) ; v1(3970,284) v1(3970,338) ; v1(4538,1637) 4538,1596.13 R66.2@4538.5,1595.63 ; R76.2@4538.5,452.63 v1@4538.5,514.5 ; v1@4538.5,815.5 R70.2@4538.5,853.3 ; U66.15@4840.53,831.68 4862.18,853.33 U66.2@4923.2,853.33 ; U68.15@4860.21,450.69 4862.18,452.66 U68.2@4923.2,452.66 ; U64.15@4860.21,1593.69 4862.18,1595.66 U64.2@4923.2,1595.66 ; U61.15@4860.21,1994.36 4862.18,1996.33 U61.2@4923.2,1996.33 ; C99.2@5207,1469 5215.63,1460.37 U86.5@5271.29,1460.37 ; R96.1@5323,1590 5432.5,1590 C98.2@5433,1590.5 5398,1625.5 R95.1@5398,1645 ; 5398,1660 R93.1@5398,1705
  Bottom Layer w50: C93.1@5880,262.74 J81.2@6060.67,262.74
  other v1: 3780,34 3372,41 5128,41 5119,69 4107,73 3900,83 3468,85 3783,97 5122,100 4606,102 5136,126 3949,133 3861,134 3733,139 3590,144 5158,145 4121,148 3467,150.34 5217,153 5187,155 3581,212 4183,233 4508,272 3773,275 3897,275 3437.27,277 3532,281 3656,289 4497,332 4448,354 3373,359 3841,359 3660,366 3793,396 4328,428 4448,428 2841,441 3107,441 3479,444 3793,458 3648,467 3553,474 5040,495 5070,510 4328,515 4538,515 3221.06,525 5040,525 3647,531 4159,535 5070,540 3522,554 5040,555 5070,570 3488,587 3235,590 3568,590 3116,592 3353,614 3533,625 3615,630 4138,670 3139,703 3355,746 4006,749 3027,753 2909,763 3762,776 3249,781 3639,813 4538,815 3976,946 3354,961 3147,964.51 3796,976 3884.5,980.89 3971,1041 2947,1049 3143,1088 3968,1099 4734,1146 3790,1160 3222,1179 3438,1184 2976,1191 3484,1231 3345,1241 2867,1249 3846.53,1257.02 3306,1287 2907,1300 4130,1301.51 4172,1301.51 4215,1301.51 3873,1347 2867,1351 3342,1365 3492,1368 5397,1494 4548.33,1977.62
  other v2: 4767.69,157.84 4811,157.84 4854.31,157.84 4767.69,201.15 4811,201.15 4854.31,201.15 4767.69,244.46 4811,244.46 4854.31,244.46 4767.69,358.17 4811,358.17 4854.31,358.17 4767.69,401.48 4811,401.48 4854.31,401.48 4767.69,444.79 4811,444.79 4854.31,444.79 4767.69,558.51 4811,558.51 4854.31,558.51 4767.69,601.81 4811,601.81 4854.31,601.81 4767.69,645.12 4811,645.12 4854.31,645.12 4767.69,758.84 4811,758.84 4854.31,758.84 4767.69,802.15 4811,802.15 4854.31,802.15 4767.69,845.45 4811,845.45 4854.31,845.45 3623,927.93 3564.93,986 3623,986 3681.07,986 3623,1044.07 4767.69,1300.84 4811,1300.84 4854.31,1300.84 4767.69,1344.15 4811,1344.15 4854.31,1344.15 4767.69,1387.46 4811,1387.46 4854.31,1387.46 4767.69,1501.17 4811,1501.17 4854.31,1501.17 4767.69,1544.48 4811,1544.48 4854.31,1544.48 4767.69,1587.79 4811,1587.79 4854.31,1587.79 4767.69,1701.51 4811,1701.51 4854.31,1701.51 4767.69,1744.81 4811,1744.81 4854.31,1744.81 4767.69,1788.12 4811,1788.12 4854.31,1788.12 4767.69,1901.84 4811,1901.84 4854.31,1901.84 4767.69,1945.15 4811,1945.15 4854.31,1945.15 4767.69,1988.45 4811,1988.45 4854.31,1988.45
  other v3: 5542,275 5581.33,275 5620.67,275 5660,275 5691,1218 5690.83,1252.5 5691,1287 5524,1297 5524,1332
  other v4: 4767.69,114.53 4811,114.53 4854.31,114.53 4767.69,287.76 4811,287.76 4854.31,287.76 4767.69,314.87 4811,314.87 4854.31,314.87 4767.69,488.1 4811,488.1 4854.31,488.1 4767.69,515.2 4811,515.2 4854.31,515.2 4767.69,688.43 4811,688.43 4854.31,688.43 4767.69,715.53 4811,715.53 4854.31,715.53 4767.69,888.76 4811,888.76 4854.31,888.76 4767.69,1257.53 4811,1257.53 4854.31,1257.53 4767.69,1430.76 4811,1430.76 4854.31,1430.76 4767.69,1457.87 4811,1457.87 4854.31,1457.87 4767.69,1631.1 4811,1631.1 4854.31,1631.1 4767.69,1658.2 4811,1658.2 4854.31,1658.2 4767.69,1831.43 4811,1831.43 4854.31,1831.43 4767.69,1858.53 4811,1858.53 4854.31,1858.53 4767.69,2031.76 4811,2031.76 4854.31,2031.76
  other v6: 4180,610 4270,690 4180,810 4360,810 4180,870 4360,870 4360,1041 4180,1050 3730.28,1093.28 4180,1110 4360,1110
  other v9: 5200,1506
GNDA_ADC: J2.34
GPIO0_7: J2.42
GPIO0_26: J1.14
GPIO0_27: J1.17
GPIO1_12: J1.12
GPIO1_13: J1.11
GPIO1_14: J1.16
GPIO1_15: J1.15
GPIO1_16: J2.15 R2.1 | length 1782.6
  Top Layer w10: J2.15@1475,75 1519,31 1593,31 1625,63 1625,368.28 1709.72,453 2061.23,453 2138.15,529.92 2138.15,756.65 2441.5,1060 R2.1@2441.5,1120
GPIO1_17: J2.23 R1.1 | length 264.2
  Top Layer w10: J2.23@1875,75 1875,83 1925,133 R1.1@1925,318.5
GPIO1_28: J2.12
GPIO1_29: J1.26
GPIO2_1: J1.18
GPIO3_19: J2.27
GPIO3_21: J2.25
I2C2_SCL: J2.19 R12.1 U6.6 | length 1610.8
  Top Layer w10: R12.1@440,628.5 445,623.5 v1(445,592) U6.6@445,524.49
  Bottom Layer w10: v1(445,592) 781,256 847.57,256 848.57,257 1595,257 1625,227 1625,125 J2.19@1675,75
I2C2_SDA: J2.20 R13.1 U6.5 | length 1485.4
  Top Layer w10: U6.5@495,524.49 v1(495,592) 495,623.5 R13.1@500,628.5
  Bottom Layer w10: v1@500.87,586.13 813.5,273.5 840.32,273.5 845.82,279 1172.18,279 1172.68,278.5 1191.32,278.5 1191.82,279 1622.12,279 1675,226.12 J2.20@1675,175
LCD_DATA0: J1.45
LCD_DATA1: J1.46
LCD_DATA2: J1.43
LCD_DATA3: J1.44
LCD_DATA4: J1.41
LCD_DATA5: J1.42
LCD_DATA6: J1.39
LCD_DATA7: J1.40
LCD_DATA8: J1.37
LCD_DATA9: J1.38
LCD_DATA10: J1.36
LCD_DATA11: J1.34
LCD_DATA12: J1.35
LCD_DATA13: J1.33
LCD_DATA14: J1.31
LCD_DATA15: J1.32
LCD_DE: J1.30
LCD_HSYNC: J1.29
LCD_PCLK: J1.28
LCD_VSYNC: J1.27
LED_SOUT: U5.22 U7.2 | length 661.8
  Top Layer w10: v1(1506,656) U7.2@1525.87,656 ; v1(1582.5,1115) U5.22@1582.5,1179.41
  Bottom Layer w10: v1(1506,656) 1558.75,656 1650,747.25 1650,1008 1582.5,1075.5 v1(1582.5,1115)
MISO: R7.2 R26.2 | length 1255.1
  Top Layer w10: R7.2@1570,388.5 1570,367 1580,357 v1(1580,345) ; v1(2557.5,785.5) R26.2@2557.5,833
  Signal Layer 2 w10: v1(1580,345) 1634,345 1685,396 2013,396 2250,633 2405.01,633 v1(2557.5,785.5)
MISO_ISO: R43.1 U22.11 | length 769.7
  Top Layer w10: U22.11@2909.41,832.5 2952.5,832.5 2984.13,800.87 3126.29,800.87 3166.03,761.14 3166.03,745.14 3249.79,661.38 3479.58,661.38 3493.71,675.5 R43.1@3593,675.5
MMC1_CLK: J1.21
MMC1_CMD: J1.20
MMC1_DAT0: J1.25
MMC1_DAT1: J1.24
MMC1_DAT2: J1.5
MMC1_DAT3: J1.6
MMC1_DAT4: J1.23
MMC1_DAT5: J1.22 R16.1 | length 264.2
  Top Layer w10: J1.22@1775,2075 1825,2025 R16.1@1825,1831.5
MMC1_DAT6: J1.3
MMC1_DAT7: J1.4
MOSI: R3.2 U22.3 | length 1362.8
  Top Layer w10: R3.2@1700,381.5 1752.5,434 2067.5,434 2156.02,522.52 2156.02,748.3 2308.1,900.37 2308.37,900.37 2318,910 2657.63,910 2660.13,907.5 U22.3@2710.59,907.5
MOSI_ISO: R23.1 U44.10 | length 790.2
  Top Layer w10: R23.1@3071.5,963 3100.34,963 3219.65,843.68 3219.65,767.35 3272,715 3457.37,715 3483.12,740.75 3521,740.75 3521,741 v1(3530,750) ; v1(3539,830) 3555.99,830 3572.41,846.42 3572.41,863.72 3573.79,865.1 U44.10@3573.79,891.51
  Bottom Layer w10: v1(3530,750) 3539,759 v1(3539,830)
MSP_RST_N: C47.2 R44.2 R47.2 TP42.1 U42.4 U44.5 | length 942.3
  Top Layer w10: 3180,1184.7 3180,1140 3207.5,1112.5 R44.2@3207.5,1039 ; TP42.1@3180,1220 3282,1220 3341.5,1279.5 R47.2@3368.82,1279.5 ; C47.2@3388.5,1341 R47.2@3388.5,1280 3388.5,1279.5 3516.4,1151.6 U42.4@3543,1151.6 ; v1(3424,1013) 3430.43,1006.57 3482.85,1006.57 3513.27,976.16 U44.5@3528.51,976.16
  Bottom Layer w10: v1(3424,1013) 3424,1064 3506,1146 v1(3506,1162)
NetC7_1: C7.1 D2.1 D3.1 D4.1 D5.1 D6.1 D7.1 D8.1 D9.1 D10.1 D11.1 D12.1 D13.1 D14.1 D15.1 D16.1 D17.1 R18.1 | length 3603.1
  Top Layer w10: R18.1@893,1272.5 943.5,1272.5 999,1217 1261,1217 1390.87,1087.13 1895.65,1087.13 D6.1@1959.52,1151 1990.53,1120 2082,1120 D14.1@2109.53,1147.53 ; D3.1@1959.52,701 1990.53,670 2080,670 D11.1@2109.53,699.53 ; D4.1@1959.52,851 1990.53,820 2084,820 D12.1@2109.53,845.53 ; D5.1@1959.52,1001 1990.53,970 2085,970 D13.1@2109.53,994.53 ; D7.1@1959.52,1301 1990.53,1270 2078.52,1270 D15.1@2109.53,1301 ; D2.1@1959.53,551 1990.53,520 2079.44,520 2109.53,550.08 D10.1@2109.53,551 ; D8.1@1959.53,1451 1990.53,1420 2078.52,1420 D16.1@2109.53,1451 ; D9.1@1959.53,1601 1990.53,1570 2078.52,1570 D17.1@2109.53,1601 D16.1@2109.53,1451 ; D10.1@2109.53,566.75 D11.1@2109.53,699.53 ; D11.1@2109.53,699.53 D11.1@2109.53,701 D12.1@2109.53,845.53 ; D12.1@2109.53,845.53 D12.1@2109.53,851 D13.1@2109.53,994.53 ; D13.1@2109.53,994.53 D13.1@2109.53,1001 D14.1@2109.53,1147.53 ; D14.1@2109.53,1147.53 D14.1@2109.53,1151 D15.1@2109.53,1301 ; D15.1@2109.53,1301 D16.1@2109.53,1451
NetC8_2: C8.2 R14.1 U4.6 | length 129
  Top Layer w10: R14.1@1420,841.5 C8.2@1480,841.5 1522.5,841.5 1528.4,847.4 U4.6@1546.54,847.4
NetC25_2: C25.2 U23.7 | length 78.3
  Top Layer w10: U23.7@3929.68,214.48 U23.7@3960.52,214.48 ; U23.7@3960.54,214.5 C25.2@4008,214.5
NetC26_1: C26.1 U23.2 | length 77.6
  Top Layer w10: C26.1@3691.5,226 3703.02,214.48 U23.2@3764.32,214.48
NetC26_2: C26.2 D22.3 L22.1 U23.1 | length 436.9
  Top Layer w10: D22.3@3467,243.24 3611.26,243.24 C26.2@3628.5,226 3662.5,260 3730,260 ; L22.1@3720.04,366 3720.04,269.96 3730,260 ; U23.1@3764.32,240.07 3749.93,240.07 3730,260
NetC28_1: C28.1 C29.1 D21.1 R28.2 R29.2 TP21.1 U23.8 | length 722.7
  Top Layer w10: R29.2@3887,386.5 3886.5,386 C29.1@3886.5,322 3907,322 3929.68,299.32 ; U23.8@3929.68,240.07 3929.68,299.32 ; TP21.1@4218,87 4137,87 4073,151 4073.5,151 4073.5,182.5 4128.59,237.59 D21.1@4139,237.59 4139,255.57 4087,307.57 4034.52,307.57 4032.03,310.06 3940.41,310.06 3929.68,299.32
NetC97_1: C97.1 R97.1 U85.1 | length 171.7
  Top Layer w10: C97.1@5140,515.5 5161.91,537.4 5214,537.4 5214,569 5228.5,583.5 R97.1@5228.5,620
NetC97_2: C97.2 D92.2 D93.2 U85.2 U85.3 | length 236.2
  Top Layer w10: C97.2@5140,452.5 5164.05,452.5 5174.14,462.6 5183,462.6 ; U85.3@5214,451.6 5214,435 5186,407 5186,370 D92.2@5244.41,370 ; U85.3@5214,462.6 U85.2@5214,500
NetC98_1: C98.1 U86.6 | length 67.3
  Bottom Layer w10: U86.6@5432.71,1460.37 5433,1460.66 C98.1@5433,1527.5
NetC99_1: C99.1 Q81.5 Q81.6 Q81.7 Q81.8 Q81.9@5353.91,664.04 R92.2 R94.2 R97.2 R98.1 R99.1 U85.6 U86.2 | length 1382.4
  Top Layer w10: R97.2@5291.5,620 v1(5291.5,576.5) 5306,562 U85.6@5306,537.4
  Bottom Layer w10: C99.1@5199,1418.5 5216.19,1401.31 U86.2@5271.29,1401.31 ; C99.1@5199,1419 5171,1419 5117,1365 5117,1005.01 5229.01,893 5350,893 v1(5356,887) 5356,844.44 ; C99.1@5208.75,1409.25 5167.43,1450.57 5167.43,1580.43 R94.2@5232,1645 ; 5232,1660 R92.2@5232,1705 ; R99.1@5308.91,844.44 5356,844.44 ; R98.1@5403.91,844.44 5356,844.44
NetD1_1: D1.1 R4.1 | length 79
  Top Layer w10: D1.1@130.47,630 R4.1@130.5,709
NetD2_2: D2.2 U5.5 | length 540.6
  Top Layer w10: U5.5@1632.5,980.59 1632.5,925.5 1830,728 1830,621.47 D2.2@1900.47,551
NetD3_2: D3.2 U5.7 | length 369.4
  Top Layer w10: U5.7@1682.5,980.59 1684,979.09 1684,927 1870,741 1870,730.28 D3.2@1899.27,701
NetD4_2: D4.2 U5.9 | length 251.2
  Top Layer w10: U5.9@1732.5,980.59 1732.5,930.5 1812.3,850.7 1900.17,850.7 D4.2@1900.47,851
NetD5_2: D5.2 U5.11 | length 229.1
  Top Layer w10: U5.11@1782.5,980.59 1782.5,931.5 1794,920 1860,920 1900.47,960.47 D5.2@1900.47,1001
NetD6_2: D6.2 U5.13 | length 104.7
  Top Layer w10: U5.13@1807.5,1179.41 1807.91,1179 1840,1179 1868,1151 D6.2@1900.47,1151
NetD7_2: D7.2 U5.15 | length 238.3
  Top Layer w10: U5.15@1757.5,1179.41 1759,1180.91 1759,1257.72 1802.28,1301 D7.2@1900.47,1301
NetD8_2: D8.2 U5.17 | length 351.5
  Top Layer w10: U5.17@1707.5,1179.41 1707.5,1258.03 D8.2@1900.47,1451
NetD9_2: D9.2 U5.19 | length 522.2
  Top Layer w10: U5.19@1657.5,1179.41 1657.5,1264.5 1850,1457 1850,1550.53 D9.2@1900.47,1601
NetD10_2: D10.2 U5.6 | length 664.1
  Top Layer w10: U5.6@1657.5,980.59 1657.5,926.5 1850,734 1850,629 1899,580 1995,580 2024,551 D10.2@2050.47,551
NetD11_2: D11.2 U5.8 | length 488.7
  Top Layer w10: U5.8@1707.5,980.59 1707.5,929.5 1907,730 2021.48,730 D11.2@2050.47,701
NetD12_2: D12.2 U5.10 | length 376.4
  Top Layer w10: U5.10@1757.5,980.59 1756.99,980.08 1756.99,931.01 1798,890 2011.48,890 D12.2@2050.47,851
NetD13_2: D13.2 U5.12 | length 299.4
  Top Layer w10: U5.12@1807.5,980.59 1807.5,1021.5 1816,1030 2021.48,1030 D13.2@2050.47,1001
NetD14_2: D14.2 U5.14 | length 365.2
  Top Layer w10: U5.14@1782.5,1179.41 1782.5,1225.5 1807,1250 1951.48,1250 D14.2@2050.47,1151
NetD15_2: D15.2 U5.16 | length 446.2
  Top Layer w10: U5.16@1732.5,1179.41 1732,1179.91 1732,1256 1816,1340 2011.48,1340 D15.2@2050.47,1301
NetD16_2: D16.2 U5.18 | length 573.1
  Top Layer w10: U5.18@1682.5,1179.41 1682.5,1260.5 1870,1448 1870,1472 1886.48,1488.48 2013,1488.48 D16.2@2050.47,1451
NetD17_2: D17.2 U5.20 | length 737.9
  Top Layer w10: U5.20@1632.5,1179.41 1632.5,1265.5 1830,1463 1830,1584 1876,1630 2021.48,1630 D17.2@2050.47,1601
NetD21_2: D21.2 L21.2 | length 86.4
  Top Layer w10: D21.2@4139,186.41 4139.91,185.5 L21.2@4225,185.5
NetD24_1: D24.1 R32.2 | length 85.4
  Top Layer w10: D24.1@3693,563.47 3776.98,563.47 R32.2@3778,564.5
NetD25_1: D25.1 T21.3 | length 99.8
  Top Layer w10: T21.3@2990,660 3002,660 3062.76,599.24 D25.1@3062.76,597.4
NetD25_2: D25.2 T21.1 | length 100.4
  Top Layer w10: T21.1@2990,460 3003.11,460 3034.21,491.1 3034.21,494.06 D25.2@3062.76,522.6
NetD41_3: D41.3 R41.2 U41.3 | length 314.9
  Top Layer w10: U41.3@3998.5,1493.41 3998.5,1528.26 4022.24,1552 v1(4050,1552)
  Bottom Layer w10: v1@4050.5,1552 R41.2@4089,1513.5 4113.75,1538.24 D41.3@4243,1538.24
NetD42_3: D42.3 R42.2 U43.5 | length 367.5
  Top Layer w10: v1(3714,1538) 3714,1493.91 U43.5@3714.5,1493.41
  Bottom Layer w10: D42.3@3458,1538.24 3458.24,1538 v1(3714,1538) 3715.5,1538 R42.2@3761.5,1492
NetD43_1: D43.1 R45.1 | length 74
  Top Layer w10: R45.1@5701.5,1336.44 D43.1@5775.47,1336.41
NetD44_1: D44.1 R48.1 | length 82.8
  Top Layer w10: D44.1@3450,1529.53 3483.98,1529.53 R48.1@3518.5,1495
NetD81_1: D81.1 R83.1 | length 188.9
  Top Layer w10: R83.1@5639.5,400 5639.7,400.2 5669.94,400.2 5669.94,424.03 5677.48,431.57 5727.51,431.57 5735.06,424.03 5735.06,402.05 5736.91,400.2 D81.1@5775.47,400.2
NetD82_1: D82.1 R84.1 | length 189.7
  Top Layer w10: R84.1@5638.5,537.97 5668.94,537.99 5668.94,513.93 5676.48,506.39 5726.51,506.39 5734.06,513.93 5734.06,535.14 5736.91,537.99 D82.1@5775.47,537.99
NetD83_1: D83.1 R85.1 | length 189
  Top Layer w10: R85.1@5639.98,675.76 5670.41,675.8 5670.41,699.8 5677.95,707.34 5727.99,707.34 5735.53,699.8 5735.53,677.17 5736.91,675.8 D83.1@5775.47,675.8
NetD84_1: D84.1 R86.1 | length 189.7
  Top Layer w10: R86.1@5638.5,813.56 5668.94,813.58 5668.94,789.52 5676.48,781.98 5726.51,781.98 5734.06,789.52 5734.06,810.73 5736.91,813.58 D84.1@5775.47,813.58
NetD85_1: D85.1 R87.1 | length 189.7
  Top Layer w10: R87.1@5638.5,1474.24 R87.1@5638.5,1474.24 5668.94,1474.2 5668.94,1498.27 5676.48,1505.81 5726.51,1505.81 5734.06,1498.27 5734.06,1477.05 5736.91,1474.2 D85.1@5775.47,1474.2
NetD86_1: D86.1 R88.1 | length 189.5
  Top Layer w10: R88.1@5638.5,1612.03 R88.1@5638.5,1612.03 5668.94,1611.99 5668.94,1588 5676.48,1580.46 5726.51,1580.46 5734.06,1588 5734.06,1609.14 5736.91,1611.99 D86.1@5775.47,1611.99
NetD87_1: D87.1 R89.1 | length 189.7
  Top Layer w10: R89.1@5638.5,1749.83 5668.94,1749.8 5668.94,1773.86 5676.48,1781.4 5726.51,1781.4 5734.06,1773.86 5734.06,1752.65 5736.91,1749.8 D87.1@5775.47,1749.8
NetD88_1: D88.1 R90.1 | length 189.6
  Top Layer w10: R90.1@5638.5,1887.62 5668.94,1887.62 5668.94,1863.59 5676.48,1856.05 5726.51,1856.05 5734.06,1863.59 5734.06,1884.73 5736.94,1887.62 D88.1@5775.43,1887.62 ; D88.1@5775.43,1887.62 D88.1@5775.47,1887.58
NetD89_2: D89.2 U81.1 U82.1 U83.1 U84.1
  other v3: 5708,100 5750,100 5708,140 5750,140 5708,180 5750,180 5708,220 5750,220 5820,439 5850,448 5820,715 5850,724 5820,1513 5850,1522 5820,1789 5850,1798
NetD91_1: D91.1 R91.2 | length 74
  Top Layer w10: R91.2@5701.5,951.35 D91.1@5775.47,951.39
NetD95_1: D95.1 R100.2 | length 74.3
  Top Layer w10: R100.2@5701.5,2024.58 5774.67,2024.58 D95.1@5775.47,2025.39
NetJ41_1: J41.1 U43.6 | length 218.6
  Top Layer w10: J41.1@3553,1618 3607,1564 3671,1564 3689.5,1545.5 U43.6@3689.5,1493.41
NetJ41_3: J41.3 R41.1 | length 744.4
  Bottom Layer w10: J41.3@3653,1618 3705,1670 3969,1670 4003,1636 4003,1595 3983.6,1575.6 3936.6,1575.6 3923.5,1562.5 3923.5,1540.5 3936,1528 4011.5,1528 R41.1@4089,1450.5
NetJ41_5: J41.5 U43.4 | length 130.2
  Top Layer w10: U43.4@3739.5,1493.41 3739.5,1561.5 3753,1575 J41.5@3753,1618
NetJ41_7: J41.7 U43.3 | length 169.4
  Top Layer w10: U43.3@3764.5,1493.41 3764.5,1543.5 3839,1618 J41.7@3853,1618
NetJ41_8: J41.8 R42.1 | length 296.4
  Top Layer w10: v1(3829,1567) 3870,1567 3903,1600 3903,1668 J41.8@3853,1718
  Bottom Layer w10: R42.1@3829,1497 v1(3829,1567)
NetJ41_10: J41.10 J41.13 | length 241.4
  Bottom Layer w10: J41.10@3953,1718 4003,1668 4103,1668 J41.13@4153,1618
NetJ41_11: J41.11 U41.4 | length 157.5
  Top Layer w10: U41.4@3973.5,1493.41 3973.5,1538.5 J41.11@4053,1618
NetJ41_12: J41.12 U41.6 | length 312.6
  Top Layer w10: U41.6@3923.5,1493.41 3923.5,1564.85 3934.25,1575.6 3963.75,1575.6 3970.35,1569 3977,1569 4003,1595 4003,1668 J41.12@4053,1718
NetJ41_14: J41.14 U41.5 | length 465.3
  Top Layer w10: U41.5@3948.5,1493.41 v1@3948.5,1552
  Bottom Layer w10: v1(3948,1552) 3988,1552 4011,1575 4173.51,1575 4197.91,1599.4 4197.91,1673.09 J41.14@4153,1718
NetL22_2: L22.2 R27.1 R30.1 | length 635
  Top Layer w10: R27.1@3557.5,98 3557.5,121.7 3523.59,121.7 3518.09,116.2 3415.91,116.2 3400.63,131.48 3400.63,337.33 3408.17,344.87 3481.83,344.87 3489.37,337.33 3489.37,329.36 3490.23,328.5 R30.1@3520,328.5 3580.5,328.5 3599.96,347.96 L22.2@3599.96,366
NetQ81_4: Q81.4 U85.5 | length 45.1
  Top Layer w10: v1(5269,500) U85.5@5314.13,500
NetQ82_4: Q82.4 U86.10 | length 76
  Bottom Layer w10: Q82.4@5428.91,1300.83 5428.91,1350.91 5432.71,1354.71 5432.71,1375.24
NetQ82_5: Q82.5 Q82.6 Q82.7 Q82.8 Q82.9@5353.91,1149 R98.2 R99.2 U86.1 | length 892.7
  Bottom Layer w10: U86.1@5271.29,1381.63 5158.63,1381.63 5135,1358 5135,1016 5240.5,910.5 5350.5,910.5 v1(5356,916) 5356,958.61 ; R99.2@5308.91,958.61 5356,958.61 ; R98.2@5403.91,958.61 5356,958.61
NetR6_1: R6.1 TP3.1 U3.6 U8.1 | length 452.9
  Top Layer w10: 1324,495 1324,447.81 1324.41,447.4 1324.41,425.59 1332.2,417.8 1388.8,417.8 1396.34,425.34 1396.34,475.34 TP3.1@1443,522 1471.63,522 1510.22,560.59 U8.1@1544.6,560.59 ; 1326,495 R6.1@1326,566.5
NetR7_1: R7.1 U8.2 | length 122
  Top Layer w10: U8.2@1544.6,535 1574,535 1583,526 1583,494 1570,481 R7.1@1570,451.5
NetR8_1: R8.1 U6.3 | length 49.2
  Top Layer w10: R8.1@415.5,255 445,284.5 445,291.97
NetR9_2: R9.2 S1.3 U1.6 U6.2 | length 1316.2
  Top Layer w10: U6.2@395,335.51 v1(395,396) ; U1.6@1062.8,478.9 v1(1062.8,552) 1062.8,624.29 R9.2@1110,671.5 1110,716 1106,720 S1.3@1106,783.5
  Bottom Layer w10: v1(395,396) 395,611 422.37,638.37 563.63,638.37 650,552 v1(1062.8,552)
NetR10_2: R10.2 S1.4 U1.2 U6.1 | length 1641.6
  Top Layer w10: U6.1@345,335.51 v1(345,396) ; U1.2@1037.2,341.1 1037.2,377.36 1096.34,436.5 1096.57,436.5 1236.02,575.94 1254.03,575.94 1261.57,583.49 1261.57,639.92 R10.2@1230,671.5 ; S1.4@1206,783.5 1206,727 1230,703 R10.2@1230,691.18
  Bottom Layer w10: v1(345,396) 362.65,396 385.53,373.13 404.47,373.13 417.87,386.53 417.87,598.42 434.33,614.87 551.13,614.87 775.68,390.32 v1(1050,390.32)
NetR11_1: R11.1 S1.2 U6.7 | length 835.5
  Top Layer w10: U6.7@395,524.49 395,474 405,464 718,464 925.5,671.5 R11.1@971.3,671.5 ; R11.1@990,671.5 990,704 1006,720 S1.2@1006,783.5
NetR15_1: R15.1 U5.23 | length 102.8
  Top Layer w10: R15.1@1530.5,1271 1530.5,1246.5 1557.5,1219.5 U5.23@1557.5,1179.41
NetR16_2: R16.2 U3.1 | length 1677
  Top Layer w10: U3.1@1324.41,372.6 1325,372.01 v1(1325,331) ; v6(1786,1729) 1825,1768 R16.2@1825,1768.5
  Bottom Layer w10: v1@1325,340.41 1325,1130 1786,1591 v6(1786,1729)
